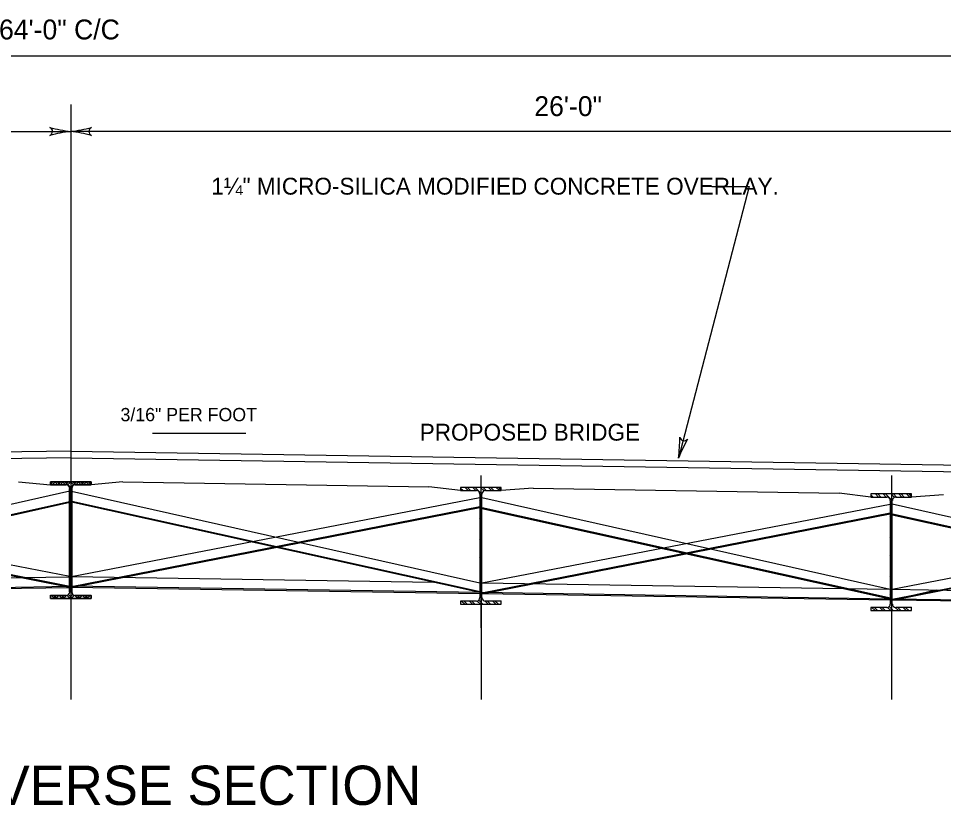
# Model space of a CAD drawing. Extents: x 10803 to 14007, y 6159 to 7440.
# Drawn here: x 13650.54 to 13672.33, y 6284.31 to 6302.86 of the extents above; entities that cross this region are included whole.
import ezdxf

# ---------------------------------------------------------------- set-up
doc = ezdxf.new("R2010")
doc.units = 0
for name, color, linetype in [('BR_P_Slab_Object', 7, 'Continuous'), ('BR_X_Slab_Object', 7, 'Continuous'), ('Default', 7, 'Continuous')]:
    doc.layers.add(name, color=color, linetype=linetype)

msp = doc.modelspace()

# ---------------------------------------------------------------- linework, layer by layer
at = {"layer": 'BR_P_Slab_Object'}
for p, q in [((13651.774, 6292.666), (13625.774, 6292.26)), ((13650.545, 6291.939), (13651.295, 6291.869))]:
    msp.add_line(p, q, dxfattribs=at)
at = {"layer": 'BR_X_Slab_Object'}
for p, q in [((13651.774, 6292.666), (13677.774, 6292.26)), ((13651.774, 6292.508), (13625.774, 6292.101)), ((13651.774, 6292.508), (13677.774, 6292.101)), ((13653.003, 6291.939), (13652.253, 6291.869)), ((13653.004, 6291.939), (13660.21, 6291.826)), ((13660.959, 6291.734), (13660.209, 6291.826)), ((13662.668, 6291.788), (13661.918, 6291.734)), ((13662.668, 6291.788), (13669.876, 6291.675)), ((13670.626, 6291.583), (13669.876, 6291.675)), ((13672.334, 6291.637), (13671.584, 6291.583))]:
    msp.add_line(p, q, dxfattribs=at)
at = {"layer": 'Default'}
for p, q in [((13623.264, 6301.979), (13680.285, 6301.979)), ((13651.774, 6300.832), (13651.774, 6286.816)), ((13629.264, 6300.196), (13651.774, 6300.196)), ((13651.286, 6300.289), (13651.285, 6300.289)), ((13674.285, 6300.196), (13651.774, 6300.196)), ((13652.262, 6300.289), (13652.263, 6300.289)), ((13667.756, 6298.896), (13666.091, 6292.499)), ((13666.879, 6298.896), (13667.756, 6298.896)), ((13655.903, 6293.077), (13653.698, 6293.077)), ((13666.304, 6292.948), (13666.304, 6292.948)), ((13651.774, 6292.272), (13651.774, 6288.521)), ((13651.774, 6292.272), (13651.774, 6288.521)), ((13651.295, 6291.869), (13651.295, 6291.942)), ((13651.295, 6291.942), (13652.253, 6291.942)), ((13651.295, 6291.88), (13651.357, 6291.942)), ((13652.253, 6291.942), (13651.295, 6291.942)), ((13651.295, 6291.942), (13651.295, 6291.869)), ((13651.345, 6291.869), (13651.295, 6291.919)), ((13651.341, 6291.869), (13651.414, 6291.942)), ((13651.472, 6291.869), (13651.4, 6291.942)), ((13651.529, 6291.869), (13651.456, 6291.942)), ((13651.468, 6291.869), (13651.541, 6291.942)), ((13651.524, 6291.869), (13651.597, 6291.942)), ((13651.656, 6291.869), (13651.583, 6291.942)), ((13651.798, 6291.784), (13651.64, 6291.942)), ((13651.652, 6291.869), (13651.725, 6291.942)), ((13651.699, 6291.86), (13651.781, 6291.942)), ((13651.75, 6291.784), (13651.908, 6291.942)), ((13651.849, 6291.86), (13651.767, 6291.942)), ((13651.897, 6291.869), (13651.824, 6291.942)), ((13651.892, 6291.869), (13651.965, 6291.942)), ((13652.024, 6291.869), (13651.951, 6291.942)), ((13652.081, 6291.869), (13652.008, 6291.942)), ((13652.019, 6291.869), (13652.092, 6291.942)), ((13652.076, 6291.869), (13652.149, 6291.942)), ((13652.208, 6291.869), (13652.135, 6291.942)), ((13652.253, 6291.88), (13652.191, 6291.942)), ((13652.203, 6291.869), (13652.253, 6291.919)), ((13652.253, 6291.942), (13652.253, 6291.869)), ((13652.253, 6291.869), (13652.253, 6291.942)), ((13661.438, 6292.091), (13661.438, 6288.502)), ((13671.108, 6292.091), (13671.108, 6286.816)), ((13651.753, 6291.723), (13642.134, 6289.564)), ((13651.667, 6291.869), (13651.295, 6291.869)), ((13651.295, 6291.869), (13651.667, 6291.869)), ((13651.667, 6291.869), (13651.667, 6291.869)), ((13651.75, 6289.348), (13651.75, 6291.786)), ((13651.75, 6291.786), (13651.75, 6289.348)), ((13651.75, 6291.727), (13651.798, 6291.775)), ((13651.798, 6291.727), (13651.75, 6291.775)), ((13651.796, 6291.723), (13661.414, 6289.564)), ((13651.798, 6291.786), (13651.798, 6289.348)), ((13651.798, 6289.348), (13651.798, 6291.786)), ((13652.253, 6291.869), (13651.882, 6291.869)), ((13651.882, 6291.869), (13652.253, 6291.869)), ((13651.882, 6291.869), (13651.882, 6291.869)), ((13661.918, 6291.807), (13660.959, 6291.807)), ((13660.959, 6291.807), (13660.959, 6291.734)), ((13661.009, 6291.734), (13660.959, 6291.784)), ((13660.959, 6291.734), (13661.331, 6291.734)), ((13661.137, 6291.734), (13661.064, 6291.807)), ((13661.193, 6291.734), (13661.12, 6291.807)), ((13661.32, 6291.734), (13661.248, 6291.807)), ((13661.463, 6291.649), (13661.304, 6291.807)), ((13661.513, 6291.725), (13661.431, 6291.807)), ((13661.561, 6291.734), (13661.488, 6291.807)), ((13661.546, 6291.734), (13661.918, 6291.734)), ((13661.546, 6291.734), (13661.546, 6291.734)), ((13661.688, 6291.734), (13661.615, 6291.807)), ((13661.745, 6291.734), (13661.672, 6291.807)), ((13661.872, 6291.734), (13661.799, 6291.807)), ((13661.918, 6291.745), (13661.856, 6291.807)), ((13661.918, 6291.734), (13661.918, 6291.807)), ((13642.13, 6289.351), (13651.748, 6291.479)), ((13651.753, 6289.713), (13642.134, 6291.568)), ((13651.75, 6291.6), (13651.798, 6291.648)), ((13651.798, 6291.6), (13651.75, 6291.648)), ((13651.75, 6291.543), (13651.798, 6291.592)), ((13651.798, 6291.543), (13651.75, 6291.592)), ((13651.75, 6291.416), (13651.798, 6291.464)), ((13651.798, 6291.416), (13651.75, 6291.464)), ((13651.796, 6289.713), (13661.414, 6291.568)), ((13661.419, 6289.351), (13651.8, 6291.479)), ((13661.414, 6291.651), (13661.414, 6289.213)), ((13661.463, 6291.592), (13661.414, 6291.64)), ((13661.463, 6291.465), (13661.414, 6291.513)), ((13661.463, 6289.213), (13661.463, 6291.651)), ((13661.463, 6291.571), (13671.081, 6289.412)), ((13671.584, 6291.656), (13670.626, 6291.656)), ((13670.626, 6291.656), (13670.626, 6291.583)), ((13670.676, 6291.583), (13670.626, 6291.633)), ((13670.626, 6291.583), (13670.998, 6291.583)), ((13670.803, 6291.583), (13670.73, 6291.656)), ((13670.86, 6291.583), (13670.787, 6291.656)), ((13670.987, 6291.583), (13670.914, 6291.656)), ((13671.129, 6291.498), (13670.971, 6291.656)), ((13671.081, 6291.5), (13671.081, 6289.062)), ((13671.129, 6291.441), (13671.081, 6291.489)), ((13671.18, 6291.574), (13671.098, 6291.656)), ((13671.129, 6289.062), (13671.129, 6291.5)), ((13671.228, 6291.583), (13671.155, 6291.656)), ((13671.213, 6291.583), (13671.584, 6291.583)), ((13671.213, 6291.583), (13671.213, 6291.583)), ((13671.355, 6291.583), (13671.282, 6291.656)), ((13671.411, 6291.583), (13671.339, 6291.656)), ((13671.539, 6291.583), (13671.466, 6291.656)), ((13671.584, 6291.594), (13671.522, 6291.656)), ((13671.584, 6291.583), (13671.584, 6291.656)), ((13642.134, 6289.33), (13651.753, 6291.458)), ((13651.753, 6289.455), (13642.134, 6291.339)), ((13651.753, 6289.476), (13642.138, 6291.359)), ((13651.75, 6291.359), (13651.798, 6291.408)), ((13651.798, 6291.359), (13651.75, 6291.408)), ((13651.75, 6291.232), (13651.798, 6291.28)), ((13651.798, 6291.232), (13651.75, 6291.28)), ((13661.414, 6289.33), (13651.796, 6291.458)), ((13651.796, 6289.476), (13661.41, 6291.359)), ((13651.796, 6289.455), (13661.414, 6291.339)), ((13661.463, 6291.408), (13661.414, 6291.457)), ((13661.463, 6291.281), (13661.414, 6291.329)), ((13661.463, 6291.224), (13661.414, 6291.273)), ((13661.463, 6289.562), (13671.081, 6291.416)), ((13671.081, 6289.179), (13661.463, 6291.307)), ((13671.085, 6289.2), (13661.467, 6291.328)), ((13671.129, 6291.314), (13671.081, 6291.362)), ((13671.129, 6291.257), (13671.081, 6291.306)), ((13671.128, 6291.42), (13680.747, 6289.261)), ((13671.128, 6289.411), (13680.747, 6291.265)), ((13651.75, 6291.176), (13651.798, 6291.224)), ((13651.798, 6291.176), (13651.75, 6291.224)), ((13651.75, 6291.048), (13651.798, 6291.097)), ((13651.798, 6291.048), (13651.75, 6291.097)), ((13651.75, 6290.992), (13651.798, 6291.04)), ((13651.798, 6290.992), (13651.75, 6291.04)), ((13661.463, 6291.097), (13661.414, 6291.145)), ((13661.463, 6291.041), (13661.414, 6291.089)), ((13661.463, 6289.325), (13671.077, 6291.208)), ((13661.463, 6289.304), (13671.081, 6291.188)), ((13671.129, 6291.13), (13671.081, 6291.178)), ((13671.129, 6291.073), (13671.081, 6291.122)), ((13680.747, 6289.028), (13671.128, 6291.156)), ((13671.128, 6289.174), (13680.743, 6291.057)), ((13671.128, 6289.153), (13680.747, 6291.037)), ((13680.751, 6289.049), (13671.133, 6291.177)), ((13651.75, 6290.864), (13651.798, 6290.913)), ((13651.798, 6290.864), (13651.75, 6290.913)), ((13651.75, 6290.808), (13651.798, 6290.856)), ((13651.798, 6290.808), (13651.75, 6290.856)), ((13661.463, 6290.913), (13661.414, 6290.962)), ((13661.463, 6290.857), (13661.414, 6290.905)), ((13661.441, 6290.872), (13661.441, 6286.816)), ((13671.129, 6290.946), (13671.081, 6290.994)), ((13671.129, 6290.889), (13671.081, 6290.938)), ((13671.129, 6290.762), (13671.081, 6290.811)), ((13651.75, 6290.681), (13651.798, 6290.729)), ((13651.798, 6290.681), (13651.75, 6290.729)), ((13651.75, 6290.624), (13651.798, 6290.672)), ((13651.798, 6290.624), (13651.75, 6290.672)), ((13661.463, 6290.729), (13661.414, 6290.778)), ((13661.463, 6290.673), (13661.414, 6290.721)), ((13661.463, 6290.546), (13661.414, 6290.594)), ((13671.129, 6290.706), (13671.081, 6290.754)), ((13671.129, 6290.578), (13671.081, 6290.627)), ((13651.75, 6290.497), (13651.798, 6290.545)), ((13651.798, 6290.497), (13651.75, 6290.545)), ((13651.75, 6290.44), (13651.798, 6290.489)), ((13651.798, 6290.44), (13651.75, 6290.489)), ((13661.463, 6290.489), (13661.414, 6290.537)), ((13661.463, 6290.362), (13661.414, 6290.41)), ((13671.129, 6290.522), (13671.081, 6290.57)), ((13671.129, 6290.395), (13671.081, 6290.443)), ((13671.129, 6290.338), (13671.081, 6290.386)), ((13651.75, 6290.313), (13651.798, 6290.361)), ((13651.798, 6290.313), (13651.75, 6290.361)), ((13651.75, 6290.256), (13651.798, 6290.305)), ((13651.798, 6290.256), (13651.75, 6290.305)), ((13651.75, 6290.129), (13651.798, 6290.177)), ((13651.798, 6290.129), (13651.75, 6290.177)), ((13661.463, 6290.305), (13661.414, 6290.354)), ((13661.463, 6290.178), (13661.414, 6290.226)), ((13661.463, 6290.121), (13661.414, 6290.17)), ((13671.129, 6290.211), (13671.081, 6290.259)), ((13671.129, 6290.154), (13671.081, 6290.202)), ((13651.75, 6290.072), (13651.798, 6290.121)), ((13651.798, 6290.072), (13651.75, 6290.121)), ((13651.75, 6289.945), (13651.798, 6289.994)), ((13651.798, 6289.945), (13651.75, 6289.994)), ((13651.75, 6289.889), (13651.798, 6289.937)), ((13651.798, 6289.889), (13651.75, 6289.937)), ((13661.463, 6289.994), (13661.414, 6290.042)), ((13661.463, 6289.937), (13661.414, 6289.986)), ((13671.129, 6290.027), (13671.081, 6290.075)), ((13671.129, 6289.97), (13671.081, 6290.019)), ((13651.75, 6289.761), (13651.798, 6289.81)), ((13651.798, 6289.761), (13651.75, 6289.81)), ((13651.75, 6289.705), (13651.798, 6289.753)), ((13651.798, 6289.705), (13651.75, 6289.753)), ((13661.463, 6289.81), (13661.414, 6289.859)), ((13661.463, 6289.754), (13661.414, 6289.802)), ((13671.129, 6289.843), (13671.081, 6289.891)), ((13671.129, 6289.786), (13671.081, 6289.835)), ((13643.22, 6289.57), (13651.753, 6289.705)), ((13651.75, 6289.578), (13651.798, 6289.626)), ((13651.798, 6289.578), (13651.75, 6289.626)), ((13651.75, 6289.521), (13651.798, 6289.569)), ((13651.798, 6289.521), (13651.75, 6289.569)), ((13660.329, 6289.57), (13651.796, 6289.705)), ((13661.463, 6289.626), (13661.414, 6289.675)), ((13661.463, 6289.57), (13661.414, 6289.618)), ((13669.996, 6289.419), (13661.463, 6289.554)), ((13671.129, 6289.659), (13671.081, 6289.707)), ((13671.129, 6289.603), (13671.081, 6289.651)), ((13671.129, 6289.475), (13671.081, 6289.524)), ((13642.134, 6289.33), (13651.753, 6289.481)), ((13642.138, 6289.303), (13651.753, 6289.455)), ((13651.816, 6289.192), (13651.721, 6289.287)), ((13651.732, 6289.192), (13651.828, 6289.287)), ((13651.749, 6289.336), (13651.798, 6289.385)), ((13651.75, 6289.394), (13651.798, 6289.442)), ((13651.798, 6289.394), (13651.75, 6289.442)), ((13651.8, 6289.336), (13651.75, 6289.385)), ((13661.414, 6289.33), (13651.796, 6289.481)), ((13661.411, 6289.303), (13651.796, 6289.455)), ((13661.463, 6289.443), (13661.414, 6289.491)), ((13661.463, 6289.386), (13661.414, 6289.434)), ((13661.463, 6289.259), (13661.414, 6289.307)), ((13671.081, 6289.178), (13661.463, 6289.33)), ((13671.078, 6289.152), (13661.463, 6289.304)), ((13671.081, 6289.402), (13669.995, 6289.42)), ((13671.129, 6289.419), (13671.081, 6289.467)), ((13671.129, 6289.291), (13671.081, 6289.34)), ((13671.129, 6289.235), (13671.081, 6289.283)), ((13679.661, 6289.268), (13671.128, 6289.403)), ((13672.172, 6289.386), (13671.129, 6289.152)), ((13651.295, 6289.192), (13651.295, 6289.272)), ((13651.295, 6289.265), (13651.667, 6289.265)), ((13651.295, 6289.25), (13651.31, 6289.265)), ((13651.667, 6289.265), (13651.295, 6289.265)), ((13651.295, 6289.265), (13651.295, 6289.192)), ((13652.253, 6289.192), (13651.295, 6289.192)), ((13651.295, 6289.192), (13652.253, 6289.192)), ((13651.392, 6289.192), (13651.319, 6289.265)), ((13651.365, 6289.192), (13651.438, 6289.265)), ((13651.448, 6289.192), (13651.375, 6289.265)), ((13651.421, 6289.192), (13651.494, 6289.265)), ((13651.576, 6289.192), (13651.503, 6289.265)), ((13651.549, 6289.192), (13651.621, 6289.265)), ((13651.632, 6289.192), (13651.559, 6289.265)), ((13651.605, 6289.192), (13651.682, 6289.269)), ((13651.759, 6289.192), (13651.684, 6289.268)), ((13651.789, 6289.192), (13651.865, 6289.268)), ((13651.943, 6289.192), (13651.867, 6289.269)), ((13651.882, 6289.265), (13652.253, 6289.265)), ((13652.253, 6289.265), (13651.882, 6289.265)), ((13651.916, 6289.192), (13651.989, 6289.265)), ((13652, 6289.192), (13651.927, 6289.265)), ((13651.973, 6289.192), (13652.046, 6289.265)), ((13652.127, 6289.192), (13652.054, 6289.265)), ((13652.1, 6289.192), (13652.173, 6289.265)), ((13652.184, 6289.192), (13652.111, 6289.265)), ((13652.157, 6289.192), (13652.23, 6289.265)), ((13652.253, 6289.25), (13652.238, 6289.265)), ((13652.253, 6289.192), (13652.253, 6289.272)), ((13652.253, 6289.265), (13652.253, 6289.192)), ((13661.331, 6289.13), (13660.959, 6289.13)), ((13660.959, 6289.13), (13660.959, 6289.057)), ((13661.056, 6289.057), (13660.983, 6289.13)), ((13661.113, 6289.057), (13661.04, 6289.13)), ((13661.24, 6289.057), (13661.167, 6289.13)), ((13661.296, 6289.057), (13661.223, 6289.13)), ((13661.424, 6289.057), (13661.348, 6289.133)), ((13661.48, 6289.057), (13661.385, 6289.152)), ((13661.464, 6289.201), (13661.414, 6289.25)), ((13661.608, 6289.057), (13661.531, 6289.134)), ((13661.918, 6289.13), (13661.546, 6289.13)), ((13661.664, 6289.057), (13661.591, 6289.13)), ((13661.791, 6289.057), (13661.718, 6289.13)), ((13661.848, 6289.057), (13661.775, 6289.13)), ((13661.918, 6289.115), (13661.902, 6289.13)), ((13661.918, 6289.057), (13661.918, 6289.137)), ((13671.129, 6289.108), (13671.081, 6289.156)), ((13671.131, 6289.049), (13671.081, 6289.099)), ((13680.747, 6289.027), (13671.128, 6289.179)), ((13680.743, 6289.001), (13671.128, 6289.153)), ((13660.959, 6289.057), (13661.918, 6289.057)), ((13670.998, 6288.979), (13670.626, 6288.979)), ((13670.626, 6288.979), (13670.626, 6288.906)), ((13670.626, 6288.906), (13671.584, 6288.906)), ((13670.723, 6288.906), (13670.65, 6288.979)), ((13670.779, 6288.906), (13670.706, 6288.979)), ((13670.907, 6288.906), (13670.834, 6288.979)), ((13670.963, 6288.906), (13670.89, 6288.979)), ((13671.09, 6288.906), (13671.014, 6288.982)), ((13671.147, 6288.906), (13671.052, 6289.001)), ((13671.274, 6288.906), (13671.198, 6288.983)), ((13671.584, 6288.979), (13671.213, 6288.979)), ((13671.331, 6288.906), (13671.258, 6288.979)), ((13671.458, 6288.906), (13671.385, 6288.979)), ((13671.515, 6288.906), (13671.442, 6288.979)), ((13671.584, 6288.964), (13671.569, 6288.979)), ((13671.584, 6288.906), (13671.584, 6288.986))]:
    msp.add_line(p, q, dxfattribs=at)
for centre, radius, start, end in [((13652.214, 6303.85), 3.68, 255.3829, 263.1374), ((13652.214, 6296.542), 3.68, 96.8626, 104.6171), ((13651.334, 6303.85), 3.68, 276.8626, 284.6171), ((13651.334, 6296.542), 3.68, 75.3829, 83.1374), ((13662.444, 6292.993), 3.68, 352.2739, 0.0284), ((13669.517, 6291.153), 3.68, 150.7942, 158.5486), ((13651.667, 6291.786), 0.0833, 0, 90), ((13651.667, 6291.786), 0.0833, 0, 90), ((13651.882, 6291.786), 0.0833, 90, 180), ((13651.882, 6291.786), 0.0833, 90, 180), ((13661.331, 6291.651), 0.0833, 0, 90), ((13661.546, 6291.651), 0.0833, 90, 180), ((13670.998, 6291.5), 0.0833, 0, 90), ((13671.213, 6291.5), 0.0833, 90, 180), ((13651.667, 6289.348), 0.0833, 270, 360), ((13651.667, 6289.348), 0.0833, 270, 360), ((13651.882, 6289.348), 0.0833, 180, 270), ((13651.882, 6289.348), 0.0833, 180, 270), ((13661.331, 6289.213), 0.0833, 270, 0), ((13661.546, 6289.213), 0.0833, 180, 270), ((13670.998, 6289.062), 0.0833, 270, 0), ((13671.213, 6289.062), 0.0833, 180, 270)]:
    msp.add_arc(centre, radius, start, end, dxfattribs=at)
for centre, major_axis, start_param, end_param in [((13651.221, 6300.196), (0.125, 0), 5.258637, 7.300638), ((13652.328, 6300.196), (-0.125, 0), 5.265733, 7.307734), ((13666.231, 6293.034), (-0.031, -0.121), 5.258637, 7.300638)]:
    msp.add_ellipse(centre, major_axis=major_axis, ratio=0.873734, start_param=start_param, end_param=end_param, dxfattribs=at)

# ---------------------------------------------------------------- texts
for s, height, p in [('64\'-0" C/C', 0.468, (13650.086, 6302.365)), ('26\'-0"', 0.468, (13662.696, 6300.559)), ('1¼" MICRO-SILICA MODIFIED CONCRETE OVERLAY.', 0.39687, (13655.086, 6298.708)), ('3/16" PER FOOT', 0.3125, (13652.948, 6293.369)), ('PROPOSED BRIDGE', 0.39687, (13659.996, 6292.912)), ('TRANSVERSE SECTION', 0.92604, (13645.787, 6284.328))]:
    msp.add_text(s, height=height, dxfattribs=at).set_placement(p)

doc.saveas('drawing.dxf')
